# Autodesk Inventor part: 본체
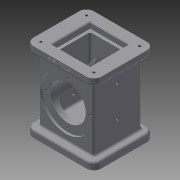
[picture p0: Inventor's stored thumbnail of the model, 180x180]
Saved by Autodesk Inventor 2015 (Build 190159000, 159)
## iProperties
Created: 2017-08
Part Number: 본체
Material: 일반
Document SubType Name: Modeling
Designer: Administrator
Density: 1 g/cm^3
Appearance: 기본값
Author: Administrator
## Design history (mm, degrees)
sketch "스케치1"
  geometry: L1 (-46, 41)-(46, 41); L2 (46, 41)-(46, -41); L3 (46, -41)-(-46, -41); L4 (-46, -41)-(-46, 41); L5 (-46, 41)-(46, -41); 2 further points
  constraints: 10 end point, 2 parallel, 1 coincident, 1 horizontal, 1 midpoint, 1 perpendicular
  dimensions: "d0" = 92 distance of L1.start L1.end; "d1" = 82 distance of L3.end L1.start
extrude "돌출1" new body sketch "스케치1" distance "d2" = 10; taper "d3" = 0 deg
sketch "스케치2"
  geometry: L1 (-37, 33)-(37, 33); L2 (37, 33)-(37, -33); L3 (37, -33)-(-37, -33); L4 (-37, -33)-(-37, 33); L5 (-37, 33)-(37, -33); 2 further points
  constraints: 10 end point, 2 parallel, 1 coincident, 1 horizontal, 1 midpoint, 1 perpendicular
  dimensions: "d4" = 74 distance of L1.start L1.end; "d5" = 66 distance of L3.end L1.start
extrude "돌출2" join sketch "스케치2" distance "d6" = 88; taper "d7" = 0 deg
sketch "스케치3"
  geometry: L1 (37, 33)-(37, -33) reference; L2 (37, -33)-(-37, -33) reference; L3 (-37, -33)-(-37, 33) reference; L4 (-37, 33)-(37, 33) reference; L5 (46, 41)-(-46, 41) reference; L6 (-46, 41)-(-46, -41) reference; L7 (-46, -41)-(46, -41) reference; L8 (46, -41)-(46, 41) reference; L9 (-46, 41)-(46, 41); L10 (46, 41)-(46, -41); L11 (46, -41)-(-46, -41); L12 (-46, -41)-(-46, 41); 1 further point
  constraints: 8 end point, 2 parallel, 1 horizontal, 1 perpendicular
extrude "돌출3" join sketch "스케치3" distance "d8" = 10; taper "d9" = 0 deg
sketch "스케치4"
  geometry: L1 (24, -24)-(-24, -24); L2 (-24, -24)-(-24, 24); L3 (-24, 24)-(24, 24); L4 (24, 24)-(24, -24); L5 (24, -24)-(-24, 24); 2 further points
  constraints: 10 end point, 2 parallel, 1 coincident, 1 horizontal, 1 midpoint, 1 perpendicular
  dimensions: "d10" = 48 distance of L1.start L1.end; "d11" = 48 distance of L3.end L1.start
extrude "돌출4" cut sketch "스케치4" distance "d12" = 16; taper "d13" = 0 deg
sketch "스케치6"
  geometry: L1 (-26, 26)-(26, 26); L2 (26, 26)-(26, -26); L3 (26, -26)-(-26, -26); L4 (-26, -26)-(-26, 26); L5 (-26, 26)-(26, -26); 2 further points
  constraints: 10 end point, 2 parallel, 1 coincident, 1 horizontal, 1 midpoint, 1 perpendicular
  dimensions: "d18" = 52 distance of L1.start L1.end; "d19" = 52 distance of L3.end L1.start
extrude "돌출6" cut sketch "스케치6" distance "d20" = 8; taper "d21" = 0 deg
sketch "스케치7" dims "d71" = 3
  geometry: L1 (-22, 22)-(22, 22); L2 (22, 22)-(22, -22); L3 (22, -22)-(-22, -22); L4 (-22, -22)-(-22, 22); L5 (-22, 22)-(22, -22); 2 further points
  constraints: 10 end point, 2 parallel, 1 coincident, 1 horizontal, 1 midpoint, 1 perpendicular
  dimensions: "d22" = 44 distance of L1.start L1.end; "d23" = 44 distance of L3.end L1.start
extrude "돌출7" cut sketch "스케치7" distance "d24" = 74; taper "d25" = 0 deg
sketch "스케치8"
  geometry: L1 (11, 98)-(63, 98) reference; L2 (37, 98)-(37, -10); L3 (83, -10)-(-9, -10) reference; C1 r 35 at (37, 44)
  constraints: 2 end point, 2 midpoint, 1 centre point, 1 vertical
  dimensions: "d26" = 70 diameter of C1; "d27" = 54 distance from line of L3 C1.centre
extrude "돌출8" cut sketch "스케치8" distance "d28" = 3; taper "d29" = 0 deg
sketch "스케치10"
  geometry: C1 r 35 at (0, 0) reference; C2 r 24 at (0, 0); 1 further point
  constraints: 1 centre point, 1 coincident
  dimensions: "d30" = 48 diameter of C2
extrude "돌출9" cut sketch "스케치10" stored distance "d31" = 3; taper "d32" = 0 deg
sketch "스케치11"
  geometry: L1 (0, 0)-(0, -29); C1 r 24 at (0, 0) reference; C2 r 35 at (0, 0) reference; 2 further points
  constraints: 2 end point, 1 coincident, 1 vertical
  dimensions: "d33" = 29 distance of L1.start L1.end
hole "구멍1" sketch "스케치11" at (0, -29) diameter "d34" = 3.242; stored, may be unused: countersink angle "d38" = 90 deg, drill point angle "d40" = 118 deg; dims "d35" = 4, "d36" = 4, "d37" = 2, "d39" = 6
fillet "모깎기1" dims "d44" = 10
fillet "모깎기2" dims "d45" = 10
sketch "스케치12"
  geometry: L1 (-46, 31)-(-46, -31) reference; L2 (-36, -41)-(36, -41) reference; L3 (46, -31)-(46, 31) reference; L4 (36, 41)-(-36, 41) reference; L5 (-26, -26)-(-26, 26) reference; L6 (-26, 26)-(26, 26) reference; L7 (26, 26)-(26, -26) reference; L8 (26, -26)-(-26, -26) reference; A1 r 10 centre (-36, 31) between (-36, 41) and (-46, 31) reference; A2 r 10 centre (-36, -31) between (-46, -31) and (-36, -41) reference; A3 r 10 centre (36, -31) between (36, -41) and (46, -31) reference; A4 r 10 centre (36, 31) between (46, 31) and (36, 41) reference; 5 further points
  constraints: 4 coincident
hole "구멍2" sketch "스케치12" at (-36, 31), (36, 31), (36, -31), (-36, -31) diameter "d46" = 3.242; stored, may be unused: countersink angle "d50" = 90 deg, drill point angle "d52" = 118 deg; dims "d47" = 4, "d48" = 4, "d49" = 2, "d51" = 6
sketch "스케치13"
  geometry: L1 (24, 24)-(24, -24) reference; L2 (24, -24)-(-24, -24) reference; L3 (-24, -24)-(-24, 24) reference; L4 (-24, 24)-(24, 24) reference; L5 (36, 41)-(-36, 41) reference; L6 (-46, 31)-(-46, -31) reference; L7 (-36, -41)-(36, -41) reference; L8 (46, -31)-(46, 31) reference; C1 r 1.621 at (36, -31) reference; C2 r 1.621 at (-36, -31) reference; C3 r 1.621 at (-36, 31) reference; C4 r 1.621 at (36, 31) reference; A1 r 10 centre (36, 31) between (46, 31) and (36, 41) reference; A2 r 10 centre (-36, 31) between (-36, 41) and (-46, 31) reference; A3 r 10 centre (-36, -31) between (-46, -31) and (-36, -41) reference; A4 r 10 centre (36, -31) between (36, -41) and (46, -31) reference; 5 further points
  constraints: 4 coincident
hole "구멍3" sketch "스케치13" at (36, -31), (-36, -31), (-36, 31), (36, 31) diameter "d53" = 3.242; stored, may be unused: countersink angle "d57" = 90 deg, drill point angle "d59" = 118 deg; dims "d54" = 4, "d55" = 4, "d56" = 2, "d58" = 6
sketch "스케치14"
  geometry: L1 (-98, 64)-(-98, 2) reference; L2 (-98, 33)-(10, 33); L3 (10, 64)-(10, 2) reference; 2 further points
  constraints: 2 end point, 2 point on line, 1 horizontal, 1 midpoint
  dimensions: "d60" = 38 distance from line of point (-28, 33) L3; "d61" = 42 distance of point (-70, 33) point (-28, 33)
hole "구멍4" sketch "스케치14" at (-28, 33), (-70, 33) diameter "d62" = 4.134; stored, may be unused: countersink angle "d66" = 90 deg, drill point angle "d68" = 118 deg; dims "d63" = 100, "d64" = 4, "d65" = 2, "d67" = 6
fillet "모깎기3" dims "d69" = 3
fillet "모깎기4" dims "d70" = 3
fillet "모깎기5" dims "d71" = 3
fillet "모깎기6" dims "d72" = 3
sketch "스케치16"
  geometry: L1 (13.757, 6.644)-(58.243, 6.644); L2 (58.243, 6.644)-(58.243, -14.644); L3 (58.243, -14.644)-(13.757, -14.644); L4 (13.757, -14.644)-(13.757, 6.644); L5 (13.757, -14.644)-(58.243, 6.644); L6 (-10, 0)-(-10, -7) reference; L7 (36, -14.644)-(36, 6.644); L8 (13.757, -4)-(58.243, -4); L9 (0, 0)-(72, 0) reference; 1 further point
  constraints: 6 end point, 4 midpoint, 2 other
  dimensions: "d73" = 46 distance between parallel lines of L6 L7; "d74" = 4 distance between parallel lines of L8 L9
feature "엠보싱1" sketch "스케치16" dims "d0" = 92, "d1" = 82, "d75" = 0.5, "d76" = 0
chamfer "모따기1" distance "d77" = 1; stored, may be unused: second distance "d78" = 2, angle "d79" = 45 deg
chamfer "모따기2" distance "d80" = 1; stored, may be unused: second distance "d81" = 2, angle "d82" = 45 deg
fillet "모깎기7" dims "d83" = 3
fillet "모깎기8" dims "d84" = 3
node "솔리드1"
mirror "대칭1"
pattern_circular "원형 패턴1" dims angle "d42" = 360 deg
mirror "대칭2"
node "투영된 루프1"
node "투영된 루프2"
node "투영된 루프3"
node "투영된 루프4"
node "투영된 루프5"
